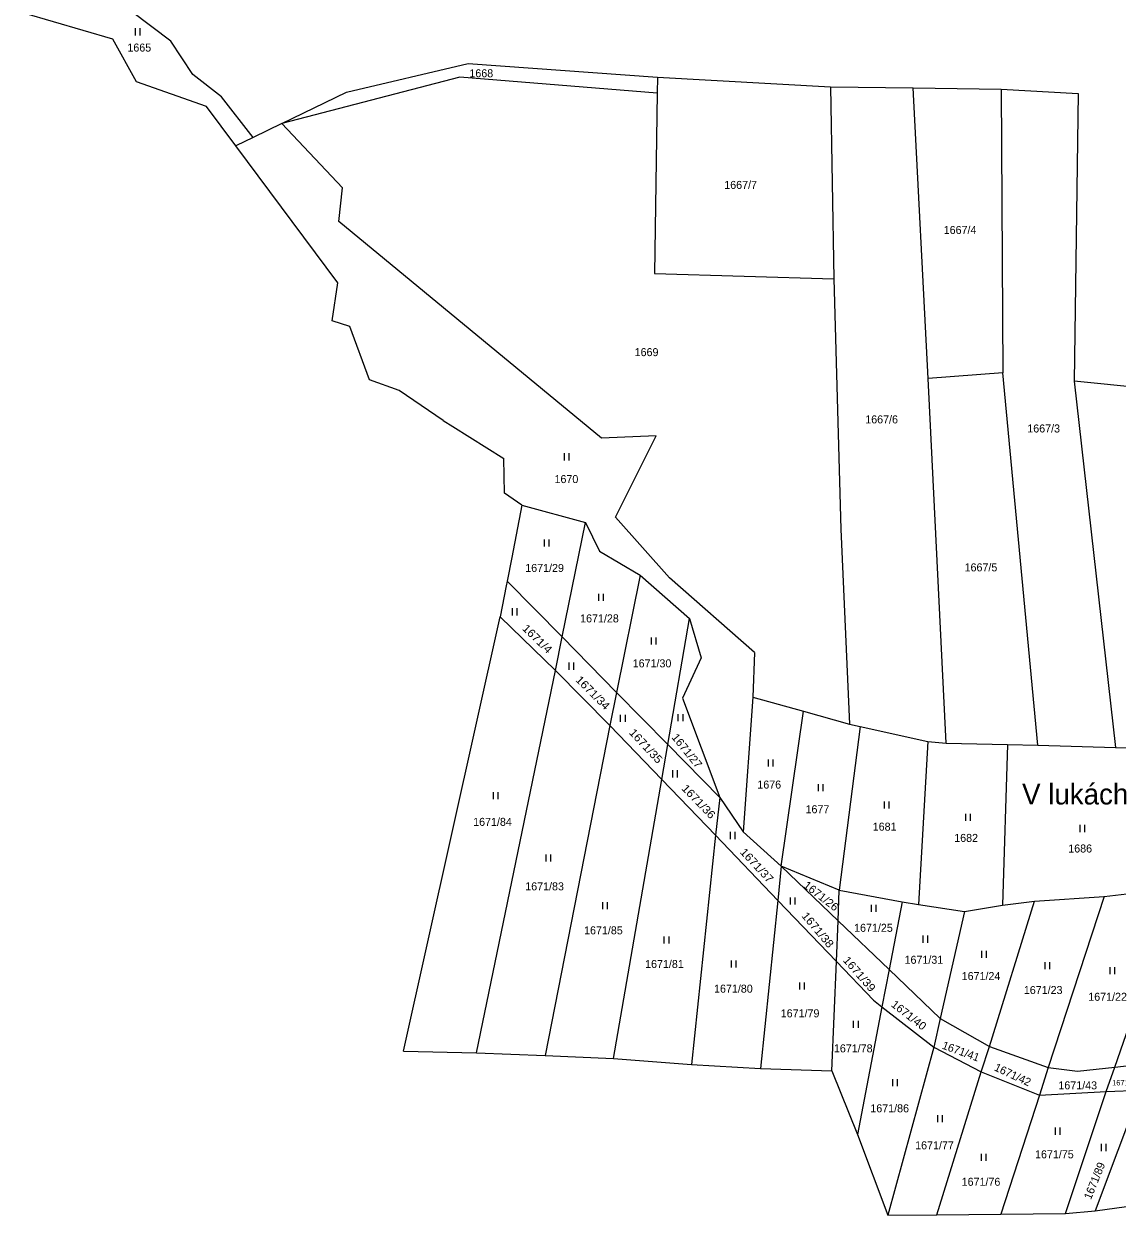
# Model space of a CAD drawing. Extents: x -820420 to -815896, y -1105820 to -1103643.
# Drawn here: x -819090.9 to -818858.6, y -1105706.9 to -1105453.8 of the extents above; entities that cross this region are included whole.
import ezdxf
from ezdxf.enums import TextEntityAlignment as Align

# ---------------------------------------------------------------- set-up
doc = ezdxf.new("R2010")
doc.units = 0
doc.header["$LTSCALE"] = 0.68
for name, color, linetype, lineweight in [('1', 7, 'Continuous', 25), ('3', 7, 'Continuous', 25), ('7', 7, 'Continuous', 13)]:
    doc.layers.add(name, color=color, linetype=linetype, lineweight=lineweight)
doc.layers.add('2', color=7, linetype='Continuous')

msp = doc.modelspace()

# ---------------------------------------------------------------- linework, layer by layer
at = {"layer": '1'}
for p, q in [((-819072.06, -1105457.08), (-819090.94, -1105451.54)), ((-819059.67, -1105457.5), (-819068.09, -1105451.15)), ((-819066.97, -1105466.13), (-819072.06, -1105457.08)), ((-819055.05, -1105464.53), (-819059.67, -1105457.5)), ((-819022.39, -1105468.31), (-818996.51, -1105462.19)), ((-818996.51, -1105462.19), (-818956.28, -1105465.12)), ((-819048.94, -1105469.27), (-819055.05, -1105464.53)), ((-818998.26, -1105465.15), (-819036.08, -1105474.95)), ((-818956.38, -1105468.5), (-818998.26, -1105465.15)), ((-818956.28, -1105465.12), (-818956.38, -1105468.5)), ((-818956.28, -1105465.12), (-818919.5, -1105467.19)), ((-819052.14, -1105471.36), (-819066.97, -1105466.13)), ((-818919.5, -1105467.19), (-818918.84, -1105507.96)), ((-818919.5, -1105467.19), (-818901.97, -1105467.42)), ((-818901.97, -1105467.42), (-818883.28, -1105467.65)), ((-818898.76, -1105529.18), (-818901.97, -1105467.42)), ((-818883.28, -1105467.65), (-818866.9, -1105468.57)), ((-818883.28, -1105467.65), (-818882.89, -1105527.93)), ((-819042.24, -1105477.97), (-819048.94, -1105469.27)), ((-819036.08, -1105474.95), (-819022.39, -1105468.31)), ((-818956.38, -1105468.5), (-818956.9, -1105506.83)), ((-818866.9, -1105468.57), (-818867.72, -1105529.73)), ((-819045.9, -1105479.71), (-819052.14, -1105471.36)), ((-819036.08, -1105474.95), (-819042.24, -1105477.97)), ((-819023.2, -1105488.64), (-819036.08, -1105474.95)), ((-819042.24, -1105477.97), (-819045.9, -1105479.71)), ((-819024.2, -1105508.79), (-819045.9, -1105479.71)), ((-819024.02, -1105495.78), (-819023.2, -1105488.64)), ((-818968.17, -1105541.79), (-819024.02, -1105495.78)), ((-818956.9, -1105506.83), (-818918.84, -1105507.96)), ((-818918.84, -1105507.96), (-818917.34, -1105561.19)), ((-819025.39, -1105516.89), (-819024.2, -1105508.79)), ((-819021.63, -1105518.07), (-819025.39, -1105516.89)), ((-819017.45, -1105529.43), (-819021.63, -1105518.07)), ((-818882.89, -1105527.93), (-818898.76, -1105529.18)), ((-818875.5, -1105607.08), (-818882.89, -1105527.93)), ((-819011.18, -1105531.66), (-819017.45, -1105529.43)), ((-818894.94, -1105606.61), (-818898.76, -1105529.18)), ((-818867.72, -1105529.73), (-818858.99, -1105607.58)), ((-818851.26, -1105531.39), (-818867.72, -1105529.73)), ((-819001.85, -1105538.07), (-819011.18, -1105531.66)), ((-819001.85, -1105538.07), (-818999.8, -1105539.34)), ((-818999.8, -1105539.34), (-818988.91, -1105546.12)), ((-818956.57, -1105541.35), (-818968.17, -1105541.79)), ((-818965.19, -1105558.62), (-818956.57, -1105541.35)), ((-818988.77, -1105553.5), (-818988.91, -1105546.12)), ((-818985.08, -1105556.08), (-818988.77, -1105553.5)), ((-818985.08, -1105556.08), (-818987.27, -1105567.21)), ((-818985.08, -1105556.08), (-818971.61, -1105559.75)), ((-818953.72, -1105571.49), (-818965.19, -1105558.62)), ((-818976.54, -1105584.05), (-818971.61, -1105559.75)), ((-818971.61, -1105559.75), (-818968.61, -1105565.8)), ((-818917.34, -1105561.19), (-818915.48, -1105602.58)), ((-818968.61, -1105565.8), (-818959.94, -1105570.92)), ((-818987.27, -1105567.21), (-818988.25, -1105572.19)), ((-818959.94, -1105570.92), (-818964.97, -1105595.84)), ((-818959.94, -1105570.92), (-818949.49, -1105580.13)), ((-818935.65, -1105587.38), (-818953.72, -1105571.49)), ((-818988.45, -1105573.19), (-818989.74, -1105579.79)), ((-818988.25, -1105572.19), (-818988.45, -1105573.19)), ((-818988.25, -1105572.19), (-818976.54, -1105584.05)), ((-819010.28, -1105672.09), (-818989.74, -1105579.79)), ((-818989.74, -1105579.79), (-818977.99, -1105591.2)), ((-818954.11, -1105606.9), (-818949.49, -1105580.13)), ((-818949.49, -1105580.13), (-818946.99, -1105588.51)), ((-818977.99, -1105591.2), (-818976.54, -1105584.05)), ((-818976.54, -1105584.05), (-818964.97, -1105595.84)), ((-818946.99, -1105588.51), (-818950.97, -1105597.04)), ((-818935.65, -1105587.38), (-818936.06, -1105596.86)), ((-818994.77, -1105672.4), (-818977.99, -1105591.2)), ((-818977.99, -1105591.2), (-818966.39, -1105602.88)), ((-818964.97, -1105595.84), (-818966.39, -1105602.88)), ((-818964.97, -1105595.84), (-818954.11, -1105606.9)), ((-818950.97, -1105597.04), (-818943.07, -1105618.15)), ((-818936.06, -1105596.86), (-818938.06, -1105625.46)), ((-818936.06, -1105596.86), (-818925.26, -1105599.85)), ((-818930, -1105632.78), (-818925.26, -1105599.85)), ((-818925.26, -1105599.85), (-818915.48, -1105602.58)), ((-818966.39, -1105602.88), (-818980.19, -1105672.96)), ((-818966.39, -1105602.88), (-818955.39, -1105614.33)), ((-818913.24, -1105603.08), (-818917.65, -1105637.89)), ((-818915.48, -1105602.58), (-818913.24, -1105603.08)), ((-818913.24, -1105603.08), (-818898.86, -1105606.26)), ((-818955.39, -1105614.33), (-818954.11, -1105606.9)), ((-818954.11, -1105606.9), (-818943.07, -1105618.15)), ((-818898.86, -1105606.26), (-818900.8, -1105640.89)), ((-818898.86, -1105606.26), (-818894.94, -1105606.61)), ((-818894.94, -1105606.61), (-818881.93, -1105606.92)), ((-818881.93, -1105606.92), (-818883, -1105641.04)), ((-818881.93, -1105606.92), (-818875.5, -1105607.08)), ((-818875.5, -1105607.08), (-818858.99, -1105607.58)), ((-818858.99, -1105607.58), (-818852.36, -1105607.72)), ((-818965.63, -1105673.63), (-818955.39, -1105614.33)), ((-818955.39, -1105614.33), (-818943.96, -1105626.2)), ((-818943.07, -1105618.15), (-818943.96, -1105626.2)), ((-818943.07, -1105618.15), (-818938.06, -1105625.46)), ((-818943.96, -1105626.2), (-818949.08, -1105674.88)), ((-818943.96, -1105626.2), (-818930.72, -1105640.04)), ((-818938.06, -1105625.46), (-818930, -1105632.78)), ((-818930, -1105632.78), (-818930.72, -1105640.04)), ((-818917.65, -1105637.89), (-818930, -1105632.78)), ((-818930, -1105632.78), (-818917.92, -1105644.35)), ((-818859.12, -1105675.46), (-818845.98, -1105637.45)), ((-818930.72, -1105640.04), (-818934.42, -1105675.75)), ((-818917.92, -1105644.35), (-818917.65, -1105637.89)), ((-818917.65, -1105637.89), (-818904.32, -1105640.36)), ((-818876.2, -1105640.22), (-818861.39, -1105639.19)), ((-818861.39, -1105639.19), (-818873.27, -1105675.51)), ((-818861.39, -1105639.19), (-818851.38, -1105638.05)), ((-818904.32, -1105640.36), (-818907.08, -1105654.73)), ((-818904.32, -1105640.36), (-818900.8, -1105640.89)), ((-818900.8, -1105640.89), (-818891.03, -1105642.37)), ((-818891.03, -1105642.37), (-818896.23, -1105665.12)), ((-818891.03, -1105642.37), (-818883, -1105641.04)), ((-818885.72, -1105671.04), (-818876.2, -1105640.22)), ((-818883, -1105641.04), (-818876.2, -1105640.22)), ((-818918.28, -1105653.01), (-818917.92, -1105644.35)), ((-818917.92, -1105644.35), (-818907.08, -1105654.73)), ((-818919.25, -1105676.22), (-818918.28, -1105653.01)), ((-818907.08, -1105654.73), (-818908.59, -1105662.63)), ((-818907.08, -1105654.73), (-818896.23, -1105665.12)), ((-818908.59, -1105662.63), (-818913.79, -1105689.75)), ((-818910.4, -1105661.22), (-818908.59, -1105662.63)), ((-818908.59, -1105662.63), (-818897.57, -1105671.24)), ((-818896.23, -1105665.12), (-818897.57, -1105671.24)), ((-818896.23, -1105665.12), (-818885.72, -1105671.04)), ((-819010.28, -1105672.09), (-818994.77, -1105672.4)), ((-818994.77, -1105672.4), (-818980.19, -1105672.96)), ((-818980.19, -1105672.96), (-818965.63, -1105673.63)), ((-818897.57, -1105671.24), (-818907.35, -1105706.91)), ((-818897.57, -1105671.24), (-818887.51, -1105676.47)), ((-818887.51, -1105676.47), (-818885.72, -1105671.04)), ((-818885.72, -1105671.04), (-818873.27, -1105675.51)), ((-818965.63, -1105673.63), (-818949.08, -1105674.88)), ((-818949.08, -1105674.88), (-818934.42, -1105675.75)), ((-818873.27, -1105675.51), (-818875.12, -1105681.39)), ((-818873.27, -1105675.51), (-818867.01, -1105676.34)), ((-818867.01, -1105676.34), (-818859.12, -1105675.46)), ((-818860.91, -1105680.64), (-818859.12, -1105675.46)), ((-818859.12, -1105675.46), (-818851.81, -1105674.65)), ((-818934.42, -1105675.75), (-818919.25, -1105676.22)), ((-818919.25, -1105676.22), (-818913.79, -1105689.75)), ((-818896.92, -1105706.87), (-818887.51, -1105676.47)), ((-818887.51, -1105676.47), (-818875.12, -1105681.39)), ((-818875.12, -1105681.39), (-818860.91, -1105680.64)), ((-818869.56, -1105706.56), (-818860.91, -1105680.64)), ((-818853.62, -1105680.32), (-818863.3, -1105706)), ((-818860.91, -1105680.64), (-818853.62, -1105680.32)), ((-818875.12, -1105681.39), (-818883.31, -1105706.7)), ((-818913.79, -1105689.75), (-818907.35, -1105706.91)), ((-818863.3, -1105706), (-818856.63, -1105705.05)), ((-818907.35, -1105706.91), (-818896.92, -1105706.87)), ((-818896.92, -1105706.87), (-818883.31, -1105706.7)), ((-818883.31, -1105706.7), (-818869.56, -1105706.56)), ((-818869.56, -1105706.56), (-818863.3, -1105706))]:
    msp.add_line(p, q, dxfattribs=at)
msp.add_lwpolyline([(-818930.72, -1105640.04), (-818918.28, -1105653.01), (-818910.4, -1105661.22)], dxfattribs=at)
at = {"layer": '3'}
for p, q in [((-819067.191, -1105456.24), (-819067.191, -1105454.74)), ((-819066.19, -1105456.24), (-819066.19, -1105454.74)), ((-818976.031, -1105546.54), (-818976.031, -1105545.04)), ((-818975.03, -1105546.54), (-818975.03, -1105545.04)), ((-818980.321, -1105564.82), (-818980.321, -1105563.32)), ((-818979.32, -1105564.82), (-818979.32, -1105563.32)), ((-818968.771, -1105576.37), (-818968.771, -1105574.87)), ((-818967.77, -1105576.37), (-818967.77, -1105574.87)), ((-818987.101, -1105579.47), (-818987.101, -1105577.97)), ((-818986.1, -1105579.47), (-818986.1, -1105577.97)), ((-818957.581, -1105585.66), (-818957.581, -1105584.16)), ((-818956.58, -1105585.66), (-818956.58, -1105584.16)), ((-818975.081, -1105591.02), (-818975.081, -1105589.52)), ((-818974.08, -1105591.02), (-818974.08, -1105589.52)), ((-818964.121, -1105602.1), (-818964.121, -1105600.6)), ((-818963.12, -1105602.1), (-818963.12, -1105600.6)), ((-818951.861, -1105601.98), (-818951.861, -1105600.48)), ((-818950.86, -1105601.98), (-818950.86, -1105600.48)), ((-818932.701, -1105611.57), (-818932.701, -1105610.07)), ((-818931.7, -1105611.57), (-818931.7, -1105610.07)), ((-818953.051, -1105613.89), (-818953.051, -1105612.39)), ((-818952.05, -1105613.89), (-818952.05, -1105612.39)), ((-818991.151, -1105618.53), (-818991.151, -1105617.03)), ((-818990.15, -1105618.53), (-818990.15, -1105617.03)), ((-818922.101, -1105616.81), (-818922.101, -1105615.31)), ((-818921.1, -1105616.81), (-818921.1, -1105615.31)), ((-818908.051, -1105620.5), (-818908.051, -1105619)), ((-818907.05, -1105620.5), (-818907.05, -1105619)), ((-818890.791, -1105623.12), (-818890.791, -1105621.62)), ((-818889.79, -1105623.12), (-818889.79, -1105621.62)), ((-818866.501, -1105625.5), (-818866.501, -1105624)), ((-818865.5, -1105625.5), (-818865.5, -1105624)), ((-818940.791, -1105626.99), (-818940.791, -1105625.49)), ((-818939.79, -1105626.99), (-818939.79, -1105625.49)), ((-818979.961, -1105631.75), (-818979.961, -1105630.25)), ((-818978.96, -1105631.75), (-818978.96, -1105630.25)), ((-818928.051, -1105640.92), (-818928.051, -1105639.42)), ((-818927.05, -1105640.92), (-818927.05, -1105639.42)), ((-818967.931, -1105641.88), (-818967.931, -1105640.38)), ((-818966.93, -1105641.88), (-818966.93, -1105640.38)), ((-818910.791, -1105642.47), (-818910.791, -1105640.97)), ((-818909.79, -1105642.47), (-818909.79, -1105640.97)), ((-818954.841, -1105649.2), (-818954.841, -1105647.7)), ((-818953.84, -1105649.2), (-818953.84, -1105647.7)), ((-818899.841, -1105649.02), (-818899.841, -1105647.52)), ((-818898.84, -1105649.02), (-818898.84, -1105647.52)), ((-818940.551, -1105654.32), (-818940.551, -1105652.82)), ((-818939.55, -1105654.32), (-818939.55, -1105652.82)), ((-818887.341, -1105652.24), (-818887.341, -1105650.74)), ((-818886.34, -1105652.24), (-818886.34, -1105650.74)), ((-818873.881, -1105654.62), (-818873.881, -1105653.12)), ((-818872.88, -1105654.62), (-818872.88, -1105653.12)), ((-818860.071, -1105655.69), (-818860.071, -1105654.19)), ((-818859.07, -1105655.69), (-818859.07, -1105654.19)), ((-818926.031, -1105658.97), (-818926.031, -1105657.47)), ((-818925.03, -1105658.97), (-818925.03, -1105657.47)), ((-818914.601, -1105667.13), (-818914.601, -1105665.63)), ((-818913.6, -1105667.13), (-818913.6, -1105665.63)), ((-818906.271, -1105679.51), (-818906.271, -1105678.01)), ((-818905.27, -1105679.51), (-818905.27, -1105678.01)), ((-818896.741, -1105687.13), (-818896.741, -1105685.63)), ((-818895.74, -1105687.13), (-818895.74, -1105685.63)), ((-818871.741, -1105689.81), (-818871.741, -1105688.31)), ((-818870.74, -1105689.81), (-818870.74, -1105688.31)), ((-818861.931, -1105693.28), (-818861.931, -1105691.78)), ((-818860.93, -1105693.28), (-818860.93, -1105691.78)), ((-818887.461, -1105695.35), (-818887.461, -1105693.85)), ((-818886.46, -1105695.35), (-818886.46, -1105693.85))]:
    msp.add_line(p, q, dxfattribs=at)

# ---------------------------------------------------------------- texts
at = {"layer": '2'}
for s, height, p in [('1665', 1.7, (-819066.4, -1105459.685)), ('1668', 1.7, (-818993.73, -1105465.145)), ('1667/7', 1.7, (-818938.62, -1105488.865)), ('1667/4', 1.7, (-818891.99, -1105498.435)), ('1669', 1.7, (-818958.61, -1105524.395)), ('1667/6', 1.7, (-818908.66, -1105538.685)), ('1667/3', 1.7, (-818874.23, -1105540.615)), ('1670', 1.7, (-818975.64, -1105551.365)), ('1671/29', 1.7, (-818980.279, -1105570.245)), ('1667/5', 1.7, (-818887.55, -1105570.125)), ('1671/28', 1.7, (-818968.619, -1105580.965)), ('1671/30', 1.7, (-818957.449, -1105590.515)), ('1676', 1.7, (-818932.54, -1105616.275)), ('1677', 1.7, (-818922.3, -1105621.515)), ('1671/84', 1.7, (-818991.349, -1105624.195)), ('1681', 1.7, (-818908.02, -1105625.215)), ('1682', 1.7, (-818890.7, -1105627.605)), ('1686', 1.7, (-818866.47, -1105629.855)), ('1671/83', 1.7, (-818980.279, -1105637.895)), ('1671/25', 1.7, (-818910.399, -1105646.705)), ('1671/85', 1.7, (-818967.779, -1105647.245)), ('1671/81', 1.7, (-818954.809, -1105654.395)), ('1671/31', 1.7, (-818899.679, -1105653.495)), ('1671/24', 1.7, (-818887.539, -1105656.955)), ('1671/80', 1.7, (-818940.159, -1105659.635)), ('1671/23', 1.7, (-818874.329, -1105659.925)), ('1671/22', 1.7, (-818860.639, -1105661.355)), ('1671/79', 1.7, (-818925.989, -1105664.875)), ('1671/78', 1.7, (-818914.689, -1105672.315)), ('1671/60', 1.14, (-818856.82, -1105679.345)), ('1671/43', 1.7, (-818866.989, -1105680.175)), ('1671/86', 1.7, (-818906.949, -1105685.055)), ('1671/77', 1.7, (-818897.419, -1105692.915)), ('1671/75', 1.7, (-818871.949, -1105694.825)), ('1671/76', 1.7, (-818887.539, -1105700.665))]:
    msp.add_text(s, height=height, dxfattribs=at).set_placement(p, align=Align.CENTER)
for s, rotation, width, p in [('1671/4', 316, 1.1, (-818982.414, -1105585.0652)), ('1671/34', 315, 1.1, (-818970.6345, -1105596.5055)), ('1671/35', 313, 1.1, (-818959.3648, -1105607.8043)), ('1671/27', 309, 1.05, (-818950.6893, -1105608.7791)), ('1671/36', 314, 1.1, (-818948.1549, -1105619.6055)), ('1671/37', 313, 1.1, (-818935.7948, -1105633.1743)), ('1671/26', 322, 1.05, (-818922.0343, -1105639.7724)), ('1671/38', 310, 1.1, (-818922.8715, -1105646.8301)), ('1671/39', 311, 1.1, (-818914.0234, -1105656.2219)), ('1671/40', 322, 1.05, (-818903.3943, -1105665.0824))]:
    msp.add_text(s, height=1.7, rotation=rotation, dxfattribs=dict(at, width=width)).set_placement(p, align=Align.CENTER)
for s, rotation, p in [('1671/41', 340, (-818892.0972, -1105672.8931)), ('1671/42', 335, (-818881.1567, -1105677.8394)), ('1671/89', 68, (-818862.6398, -1105699.9164))]:
    msp.add_text(s, height=1.7, rotation=rotation, dxfattribs=at).set_placement(p, align=Align.CENTER)
at = {"layer": '7'}
msp.add_text('V lukách', height=4.4, dxfattribs=at).set_placement((-818867.53, -1105619.65), align=Align.CENTER)

doc.saveas('drawing.dxf')
